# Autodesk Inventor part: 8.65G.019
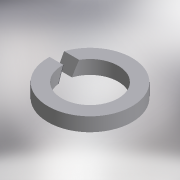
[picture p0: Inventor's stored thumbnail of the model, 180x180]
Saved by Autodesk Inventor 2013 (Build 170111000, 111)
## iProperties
Shininess: 25.0
Length Units: 11269
Angle Units: 11279
Time Units: 11290
Mass Units: 11283
Length Display Precision: 3
Angle Display Precision: 2
Created: 2001-04
Material: Steel, Mild
Description: Шайба 8.65Г.019 ГОСТ 6402-70
Document SubType Name: Modeling
Designer: tevgeniy
Density: 7.86 g/cm^3
Density: 0.0
Volumn: 0.0
Area: 0.0
PropertySet Name: Model Information
Control State: 0
Master: False
Checked Out: False
Last Check In Date: 2008-10-15
Checked Out Date: 2008-10-15
Author: tevgeniy
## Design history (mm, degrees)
node "ExtrusionBlind1" dims "d2" = 2, "d3" = 0
  sketch "Sketch1"
    geometry: C1 r 6.1 at (-266.435, -313.047)
    constraints: 1 centre point, 1 other
    dimensions: "d1" = 12.2 diameter of C1
node "Hole1" dims "d5" = 8.2, "d6" = 4, "d7" = 2, "d8" = 60 deg, "d9" = 8, "d10" = 118 deg
  sketch "Sketch2"
    geometry: C1 r 6.1 at (0, 0) reference
node "WorkAxis1"
workplane "Work Plane1"
workplane "Work Plane2"
node "WorkPlane1"
node "ExtrusionToFace1" dims "d18" = 0.13, "d19" = 0
  sketch "Sketch3"
    geometry: L1 (-17.369, -0.228)-(-17.369, -2); L2 (-15.369, 0.5)-(-17.369, -0.228); L3 (-15.369, -1.272)-(-15.369, 0.5); L4 (-17.369, -2)-(-15.369, -1.272); L5 (-7.684, 0)-(-25.053, 0); C1 r 6.1 at (-15.369, 0); C2 r 6.1 at (-17.369, 0)
    constraints: 10 end point, 2 centre point, 2 parallel, 1 vertical
    dimensions: "d13" = 0 horizontal distance of L2.start C1.centre; "d15" = 0 horizontal distance of L1.start C2.centre; "d17" = 160 deg angle of L4 L5
body "Solid1"
other parameters: "d0" = 12.2 (derived), "d4" = 0, "d11" = 0, "d12" = 0 (derived), "d14" = 0 (derived), "d16" = 160 deg (derived)
